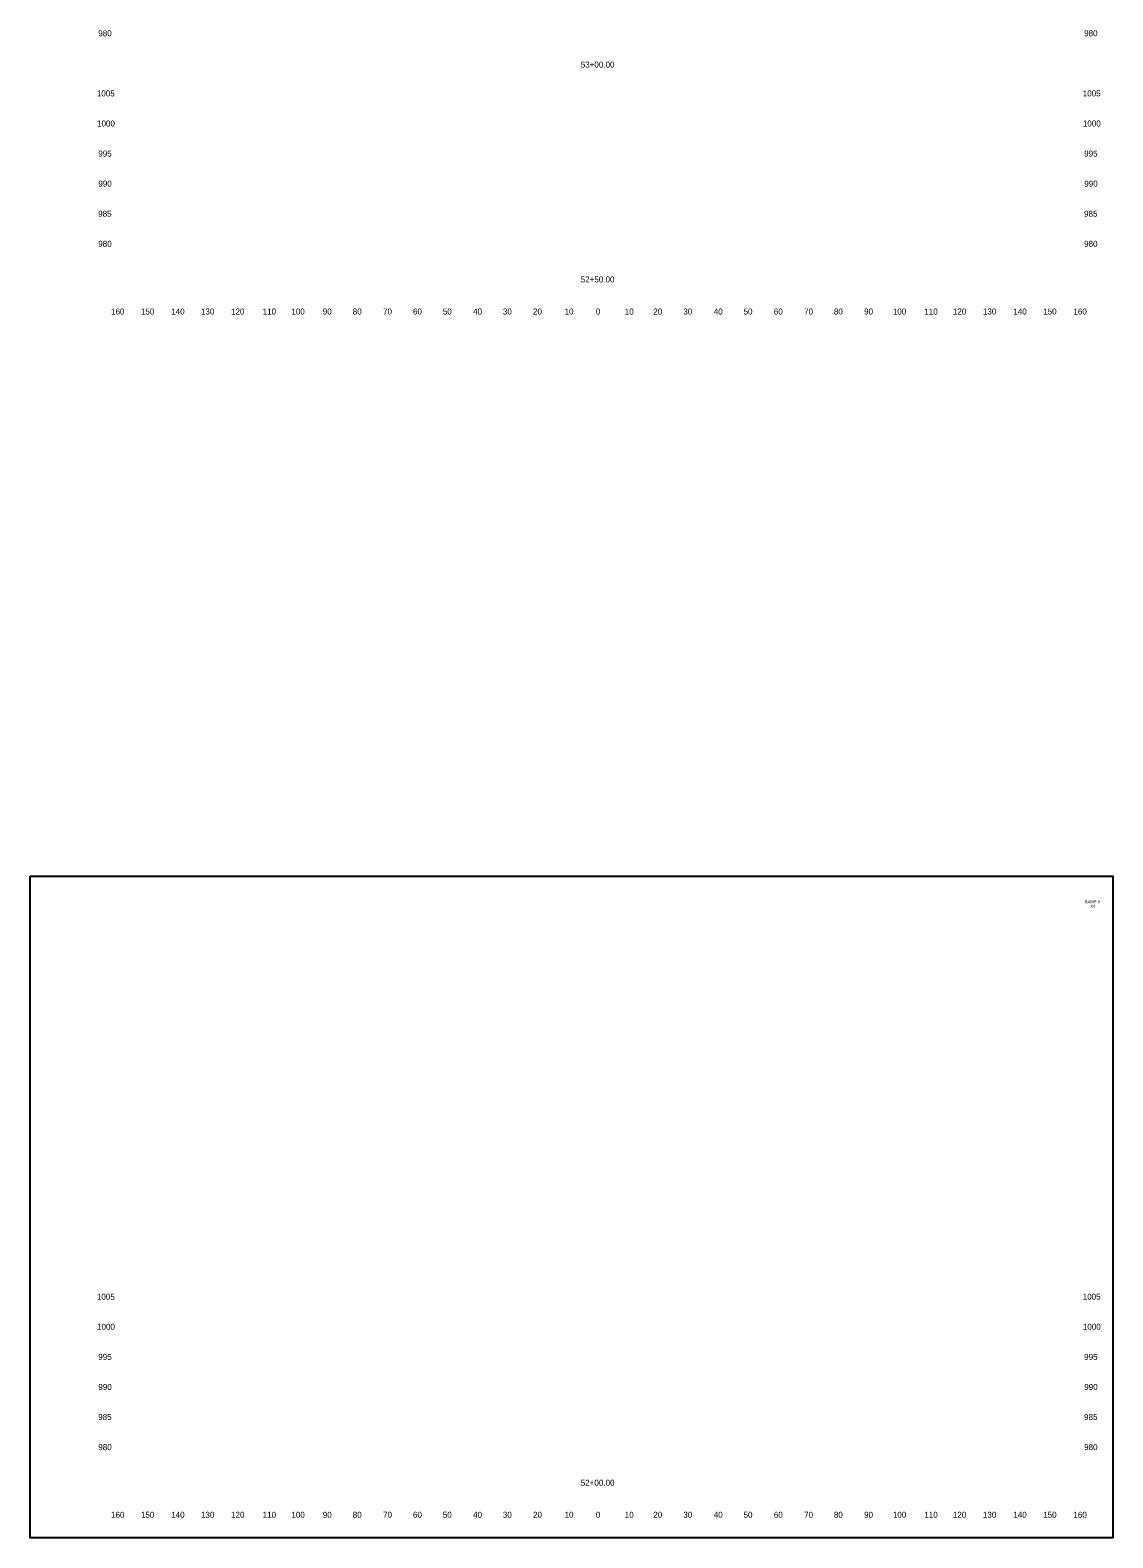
# Model space of a CAD drawing. Extents: x 4970 to 5331, y 4591 to 6811.
# Drawn here: x 4971 to 5331, y 4591 to 5092 of the extents above; entities that cross this region are included whole.
import ezdxf

# ---------------------------------------------------------------- set-up
doc = ezdxf.new("R2010")
doc.units = 0
for name, color, linetype in [('RD_SHT_ID', 7, 'Continuous'), ('RD_SHT_IplotShp', 7, 'Continuous'), ('RD_XS_TX_Offset', 7, 'Continuous'), ('RD_XS_TX_Station', 7, 'Continuous')]:
    doc.layers.add(name, color=color, linetype=linetype)

msp = doc.modelspace()

# ---------------------------------------------------------------- linework, layer by layer
at = {"layer": 'RD_SHT_IplotShp'}
msp.add_lwpolyline([(4971.21, 4810.84), (5331.21, 4810.84), (5331.21, 4590.84), (4971.21, 4590.84)], close=True, dxfattribs=at)

# ---------------------------------------------------------------- texts
at = {"layer": 'RD_SHT_ID'}
for s, p in [('RAMP 9', (5321.78, 4801.8)), ('X0', (5323.7, 4800.3))]:
    msp.add_text(s, height=1, dxfattribs=at).set_placement(p)
at = {"layer": 'RD_XS_TX_Offset'}
for s, p in [('980', (4993.86, 5090)), ('980', (5321.66, 5090)), ('1005', (4993.4, 5070)), ('1005', (5321.2, 5070)), ('1000', (4993.44, 5060)), ('1000', (5321.24, 5060)), ('995', (4993.86, 5050)), ('995', (5321.66, 5050)), ('990', (4993.89, 5040)), ('990', (5321.69, 5040)), ('985', (4993.83, 5030)), ('985', (5321.63, 5030)), ('980', (4993.86, 5020)), ('980', (5321.66, 5020)), ('160', (4998.1, 4997.5)), ('150', (5008.04, 4997.5)), ('140', (5018.1, 4997.5)), ('130', (5027.99, 4997.5)), ('120', (5038.01, 4997.5)), ('110', (5048.51, 4997.5)), ('100', (5058.07, 4997.5)), ('90', (5068.5, 4997.5)), ('80', (5078.46, 4997.5)), ('70', (5088.54, 4997.5)), ('60', (5098.5, 4997.5)), ('50', (5108.43, 4997.5)), ('40', (5118.5, 4997.5)), ('30', (5128.39, 4997.5)), ('20', (5138.4, 4997.5)), ('10', (5148.91, 4997.5)), ('0', (5159.3, 4997.5)), ('0', (5159.3, 4997.5)), ('10', (5168.91, 4997.5)), ('20', (5178.4, 4997.5)), ('30', (5188.39, 4997.5)), ('40', (5198.5, 4997.5)), ('50', (5208.43, 4997.5)), ('60', (5218.5, 4997.5)), ('70', (5228.54, 4997.5)), ('80', (5238.46, 4997.5)), ('90', (5248.5, 4997.5)), ('100', (5258.07, 4997.5)), ('110', (5268.51, 4997.5)), ('120', (5278.01, 4997.5)), ('130', (5287.99, 4997.5)), ('140', (5298.1, 4997.5)), ('150', (5308.04, 4997.5)), ('160', (5318.1, 4997.5)), ('1005', (4993.4, 4670)), ('1005', (5321.2, 4670)), ('1000', (4993.44, 4660)), ('1000', (5321.24, 4660)), ('995', (4993.86, 4650)), ('995', (5321.66, 4650)), ('990', (4993.89, 4640)), ('990', (5321.69, 4640)), ('985', (4993.83, 4630)), ('985', (5321.63, 4630)), ('980', (4993.86, 4620)), ('980', (5321.66, 4620)), ('160', (4998.1, 4597.5)), ('150', (5008.04, 4597.5)), ('140', (5018.1, 4597.5)), ('130', (5027.99, 4597.5)), ('120', (5038.01, 4597.5)), ('110', (5048.51, 4597.5)), ('100', (5058.07, 4597.5)), ('90', (5068.5, 4597.5)), ('80', (5078.46, 4597.5)), ('70', (5088.54, 4597.5)), ('60', (5098.5, 4597.5)), ('50', (5108.43, 4597.5)), ('40', (5118.5, 4597.5)), ('30', (5128.39, 4597.5)), ('20', (5138.4, 4597.5)), ('10', (5148.91, 4597.5)), ('0', (5159.3, 4597.5)), ('0', (5159.3, 4597.5)), ('10', (5168.91, 4597.5)), ('20', (5178.4, 4597.5)), ('30', (5188.39, 4597.5)), ('40', (5198.5, 4597.5)), ('50', (5208.43, 4597.5)), ('60', (5218.5, 4597.5)), ('70', (5228.54, 4597.5)), ('80', (5238.46, 4597.5)), ('90', (5248.5, 4597.5)), ('100', (5258.07, 4597.5)), ('110', (5268.51, 4597.5)), ('120', (5278.01, 4597.5)), ('130', (5287.99, 4597.5)), ('140', (5298.1, 4597.5)), ('150', (5308.04, 4597.5)), ('160', (5318.1, 4597.5))]:
    msp.add_text(s, height=2, dxfattribs=at).set_placement(p)
at = {"layer": 'RD_XS_TX_Station'}
for s, p in [('53+00.00', (5154.28, 5079.58)), ('52+50.00', (5154.26, 5008.16)), ('52+00.00', (5154.29, 4608.16))]:
    msp.add_text(s, height=2, dxfattribs=at).set_placement(p)

doc.saveas('drawing.dxf')
